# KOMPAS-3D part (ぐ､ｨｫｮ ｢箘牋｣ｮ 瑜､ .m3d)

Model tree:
1. Эскиз:1
2. Операция выдавливания:1
     Расстояние 1 = 5
3. Эскиз:2
4. Вырезать элемент выдавливания:1
     Расстояние 1 = 2.5
5. Эскиз:3
6. Операция выдавливания:2
     Расстояние 1 = 8
7. Фаска:1
     Угол = 45; Длина 1 = 1.5; Длина 2 = 1.5
8. Эскиз:4
9. Вырезать элемент выдавливания:2
     Расстояние 1 = 1.25
10. Фаска:2
     Угол = 45; Длина 1 = 1.25; Длина 2 = 1.25
11. Эскиз:6
12. Эскиз:7
13. Вырезать элемент выдавливания:4
     Расстояние 1 = 3.75
14. Скругление:1
     Радиус = 0.5
15. Фаска:3
     Угол = 45; Длина 1 = 1; Длина 2 = 1
16. Фаска:4
     Угол = 45; Длина 1 = 0.5; Длина 2 = 0.5
